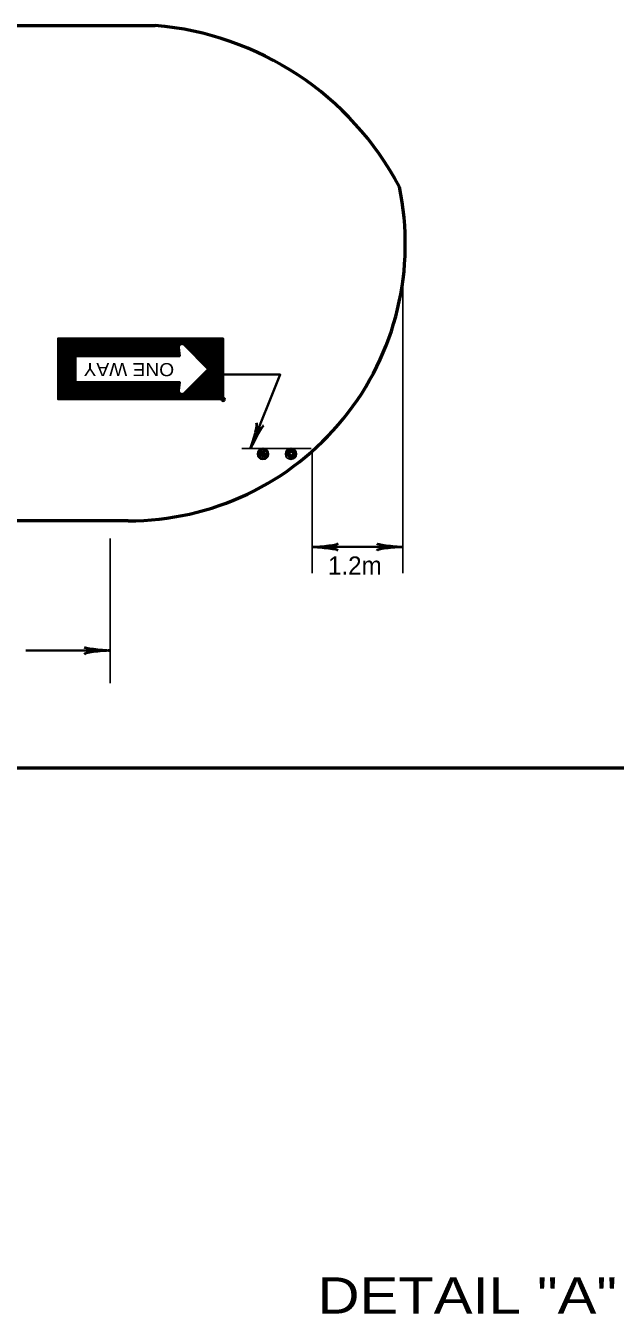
# Model space of a CAD drawing. Extents: x -198 to 658, y -402 to 142.
# Drawn here: x -14.1 to 64.2, y -213 to -43.8 of the extents above; entities that cross this region are included whole.
import ezdxf
from ezdxf.enums import TextEntityAlignment as Align

# ---------------------------------------------------------------- set-up
doc = ezdxf.new("R2010")
doc.units = 0
doc.header["$LTSCALE"] = 0.96
doc.header["$PDMODE"] = 32
doc.header["$PDSIZE"] = 0.48
doc.layers.add('1', color=7, linetype='Continuous', lineweight=35)
doc.layers.add('4', color=7, linetype='Continuous', lineweight=25)

msp = doc.modelspace()

# ---------------------------------------------------------------- linework, layer by layer
at = {"layer": '1', "lineweight": 53}
for p, q in [((-105.2517, -43.8238), (3.1359, -43.8238)), ((-0.4604, -109.4838), (-56.3544, -109.4838)), ((-105.2517, -142.2238), (234.6408, -142.2238))]:
    msp.add_line(p, q, dxfattribs=at)
at = {"layer": '1', "lineweight": 25}
for p, q in [((35.9565, -116.4304), (35.9565, -77.8663)), ((23.8168, -99.9048), (14.6368, -99.9048)), ((23.9356, -116.4304), (23.9356, -100.2786)), ((-2.849, -131.0158), (-2.849, -111.8158))]:
    msp.add_line(p, q, dxfattribs=at)
at = {"layer": '1'}
for p, q in [((-5.2152, -85.3175), (-9.7512, -89.8535)), ((-5.3832, -85.3175), (-9.7512, -89.6855)), ((-5.5512, -85.3175), (-9.7512, -89.5175)), ((-5.6952, -85.3175), (-9.7512, -89.3495)), ((-5.8632, -85.3175), (-9.7512, -89.2055)), ((-6.0312, -85.3175), (-9.7512, -89.0375)), ((-6.1992, -85.3175), (-9.7512, -88.8695)), ((-6.3432, -85.3175), (-9.7512, -88.7015)), ((-6.5112, -85.3175), (-9.7512, -88.5335)), ((-6.6792, -85.3175), (-9.7512, -88.3895)), ((-6.8472, -85.3175), (-9.7512, -88.2215)), ((-7.0152, -85.3175), (-9.7512, -88.0535)), ((-7.1592, -85.3175), (-9.7512, -87.8855)), ((-7.3272, -85.3175), (-9.7512, -87.7175)), ((-7.4952, -85.3175), (-9.7512, -87.5735)), ((-7.6632, -85.3175), (-9.7512, -87.4055)), ((-7.8312, -85.3175), (-9.7512, -87.2375)), ((-7.9752, -85.3175), (-9.7512, -87.0695)), ((-8.1432, -85.3175), (-9.7512, -86.9255)), ((-8.3112, -85.3175), (-9.7512, -86.7575)), ((-8.4792, -85.3175), (-9.7512, -86.5895)), ((-8.6232, -85.3175), (-9.7512, -86.4215)), ((-8.7912, -85.3175), (-9.7512, -86.2535)), ((-8.9592, -85.3175), (-9.7512, -86.1095)), ((-9.1272, -85.3175), (-9.7512, -85.9415)), ((-9.2952, -85.3175), (-9.7512, -85.7735)), ((-9.4392, -85.3175), (-9.7512, -85.6055)), ((-9.6072, -85.3175), (-9.7512, -85.4375)), ((-5.0472, -85.3175), (-7.3752, -87.6455)), ((-4.8792, -85.3175), (-7.2072, -87.6455)), ((-4.7352, -85.3175), (-7.0392, -87.6455)), ((-4.5672, -85.3175), (-6.8952, -87.6455)), ((-4.3992, -85.3175), (-6.7272, -87.6455)), ((-4.2312, -85.3175), (-6.5592, -87.6455)), ((-4.0632, -85.3175), (-6.3912, -87.6455)), ((-3.9192, -85.3175), (-6.2472, -87.6455)), ((-3.7512, -85.3175), (-6.0792, -87.6455)), ((-3.5832, -85.3175), (-5.9112, -87.6455)), ((-3.4152, -85.3175), (-5.7432, -87.6455)), ((-3.2472, -85.3175), (-5.5752, -87.6455)), ((-3.1032, -85.3175), (-5.4312, -87.6455)), ((-2.9352, -85.3175), (-5.2632, -87.6455)), ((-2.7672, -85.3175), (-5.0952, -87.6455)), ((-2.5992, -85.3175), (-4.9272, -87.6455)), ((-2.4552, -85.3175), (-4.7592, -87.6455)), ((-2.2872, -85.3175), (-4.6152, -87.6455)), ((-2.1192, -85.3175), (-4.4472, -87.6455)), ((-1.9512, -85.3175), (-4.2792, -87.6455)), ((-1.7832, -85.3175), (-4.1112, -87.6455)), ((-1.6392, -85.3175), (-3.9432, -87.6455)), ((-1.4712, -85.3175), (-3.7992, -87.6455)), ((-1.3032, -85.3175), (-3.6312, -87.6455)), ((-1.1352, -85.3175), (-3.4632, -87.6455)), ((-0.9672, -85.3175), (-3.2952, -87.6455)), ((-0.8232, -85.3175), (-3.1512, -87.6455)), ((-0.6552, -85.3175), (-2.9832, -87.6455)), ((-0.4872, -85.3175), (-2.8152, -87.6455)), ((-0.3192, -85.3175), (-2.6472, -87.6455)), ((-0.1752, -85.3175), (-2.4792, -87.6455)), ((-0.0072, -85.3175), (-2.3352, -87.6455)), ((0.1608, -85.3175), (-2.1672, -87.6455)), ((0.3288, -85.3175), (-1.9992, -87.6455)), ((0.4968, -85.3175), (-1.8312, -87.6455)), ((0.6408, -85.3175), (-1.6632, -87.6455)), ((0.8088, -85.3175), (-1.5192, -87.6455)), ((0.9768, -85.3175), (-1.3512, -87.6455)), ((1.1448, -85.3175), (-1.1832, -87.6455)), ((1.3128, -85.3175), (-1.0152, -87.6455)), ((1.4568, -85.3175), (-0.8712, -87.6455)), ((1.6248, -85.3175), (-0.7032, -87.6455)), ((1.7928, -85.3175), (-0.5352, -87.6455)), ((1.9608, -85.3175), (-0.3672, -87.6455)), ((2.1288, -85.3175), (-0.1992, -87.6455)), ((2.2728, -85.3175), (-0.0552, -87.6455)), ((2.4408, -85.3175), (0.1128, -87.6455)), ((2.6088, -85.3175), (0.2808, -87.6455)), ((2.7768, -85.3175), (0.4488, -87.6455)), ((2.9208, -85.3175), (0.6168, -87.6455)), ((3.0888, -85.3175), (0.7608, -87.6455)), ((3.2568, -85.3175), (0.9288, -87.6455)), ((3.4248, -85.3175), (1.0968, -87.6455)), ((3.5928, -85.3175), (1.2648, -87.6455)), ((3.7368, -85.3175), (1.4328, -87.6455)), ((3.9048, -85.3175), (1.5768, -87.6455)), ((4.0728, -85.3175), (1.7448, -87.6455)), ((4.2408, -85.3175), (1.9128, -87.6455)), ((4.4088, -85.3175), (2.0808, -87.6455)), ((4.5528, -85.3175), (2.2248, -87.6455)), ((4.7208, -85.3175), (2.3928, -87.6455)), ((4.8888, -85.3175), (2.5608, -87.6455)), ((5.0568, -85.3175), (2.7288, -87.6455)), ((5.2248, -85.3175), (2.8968, -87.6455)), ((5.3688, -85.3175), (3.0408, -87.6455)), ((5.5368, -85.3175), (3.2088, -87.6455)), ((5.7048, -85.3175), (3.3768, -87.6455)), ((5.8728, -85.3175), (3.5448, -87.6455)), ((6.0168, -85.3175), (3.7128, -87.6455)), ((6.1848, -85.3175), (3.8568, -87.6455)), ((6.3528, -85.3175), (4.0248, -87.6455)), ((6.5208, -85.3175), (4.1928, -87.6455)), ((6.6888, -85.3175), (4.3608, -87.6455)), ((6.8328, -85.3175), (4.5288, -87.6455)), ((7.0008, -85.3175), (4.6728, -87.6455)), ((7.1688, -85.3175), (4.8408, -87.6455)), ((7.3368, -85.3175), (6.5928, -86.0615)), ((7.5048, -85.3175), (6.7608, -86.0615)), ((7.6488, -85.3175), (6.8808, -86.0855)), ((6.9048, -86.1095), (10.1688, -89.3735)), ((7.8168, -85.3175), (6.9528, -86.1575)), ((7.9848, -85.3175), (7.0488, -86.2535)), ((8.1528, -85.3175), (7.1208, -86.3255)), ((8.2968, -85.3175), (7.2168, -86.4215)), ((8.4648, -85.3175), (7.2888, -86.4935)), ((8.6328, -85.3175), (7.3608, -86.5655)), ((8.8008, -85.3175), (7.4568, -86.6615)), ((8.9688, -85.3175), (7.5288, -86.7335)), ((9.1128, -85.3175), (7.6248, -86.8295)), ((9.2808, -85.3175), (7.6968, -86.9015)), ((9.4488, -85.3175), (7.7688, -86.9735)), ((9.6168, -85.3175), (7.8648, -87.0695)), ((9.7848, -85.3175), (7.9368, -87.1415)), ((9.9288, -85.3175), (8.0328, -87.2375)), ((10.0968, -85.3175), (8.1048, -87.3095)), ((10.2648, -85.3175), (8.1768, -87.3815)), ((10.4328, -85.3175), (8.2728, -87.4775)), ((10.6008, -85.3175), (8.3448, -87.5495)), ((10.7448, -85.3175), (8.4408, -87.6455)), ((10.9128, -85.3175), (8.5128, -87.7175)), ((11.0808, -85.3175), (8.5848, -87.7895)), ((11.2488, -85.3175), (8.6808, -87.8855)), ((11.3928, -85.3175), (8.7528, -87.9575)), ((11.5608, -85.3175), (8.8488, -88.0295)), ((11.7288, -85.3175), (8.9208, -88.1255)), ((11.8968, -85.3175), (8.9928, -88.1975)), ((12.0648, -85.3175), (9.0888, -88.2935)), ((12.1368, -85.3895), (9.1608, -88.3655)), ((12.1368, -85.5575), (9.2568, -88.4375)), ((12.1368, -85.7255), (9.3288, -88.5335)), ((12.1368, -85.8695), (9.4008, -88.6055)), ((12.1368, -86.0375), (9.4968, -88.7015)), ((12.1368, -86.2055), (9.5688, -88.7735)), ((-7.4472, -87.7175), (-9.7512, -90.0215)), ((-7.4472, -87.8855), (-9.7512, -90.1655)), ((6.2808, -86.3735), (5.0088, -87.6455)), ((6.2808, -86.5415), (5.1768, -87.6455)), ((6.2808, -86.6855), (5.3208, -87.6455)), ((6.3048, -86.8295), (5.4888, -87.6455)), ((6.3048, -86.9735), (5.6568, -87.6455)), ((6.3288, -87.1415), (5.8248, -87.6455)), ((6.3288, -87.2855), (5.9928, -87.6455)), ((6.3528, -87.4295), (6.1368, -87.6455)), ((12.1368, -87.5015), (6.2808, -93.3815)), ((6.3528, -87.5735), (6.3048, -87.6455)), ((12.1368, -87.6695), (6.4248, -93.3815)), ((12.1368, -87.8375), (6.5928, -93.3815)), ((12.1368, -86.3735), (9.6408, -88.8455)), ((12.1368, -86.5415), (9.7368, -88.9415)), ((12.1368, -86.6855), (9.8088, -89.0135)), ((12.1368, -86.8535), (9.9048, -89.1095)), ((12.1368, -87.0215), (9.9768, -89.1815)), ((12.1368, -87.1895), (10.0488, -89.2535)), ((12.1368, -87.3575), (10.1448, -89.3495)), ((-7.4472, -88.0535), (-9.7512, -90.3335)), ((-7.4472, -88.1975), (-9.7512, -90.5015)), ((-7.4472, -88.3655), (-9.7512, -90.6695)), ((-7.4472, -88.5335), (-9.7512, -90.8135)), ((-7.4472, -88.7015), (-9.7512, -90.9815)), ((-7.4472, -88.8455), (-9.7512, -91.1495)), ((-7.4472, -89.0135), (-9.7512, -91.3175)), ((-7.4472, -89.1815), (-9.7512, -91.4855)), ((-7.4472, -89.3495), (-9.7512, -91.6295)), ((-7.4472, -89.5175), (-9.7512, -91.7975)), ((12.1368, -88.0055), (6.7608, -93.3815)), ((10.1688, -89.3735), (6.9048, -92.6135)), ((12.1368, -88.1495), (6.9288, -93.3815)), ((12.1368, -88.3175), (7.0968, -93.3815)), ((12.1368, -88.4855), (7.2408, -93.3815)), ((12.1368, -88.6535), (7.4088, -93.3815)), ((12.1368, -88.8215), (7.5768, -93.3815)), ((12.1368, -88.9655), (7.7448, -93.3815)), ((12.1368, -89.1335), (7.9128, -93.3815)), ((12.1368, -89.3015), (8.0568, -93.3815)), ((12.1368, -89.4695), (8.2248, -93.3815)), ((12.1368, -89.6375), (8.3928, -93.3815)), ((-7.4472, -89.6615), (-9.7512, -91.9655)), ((-7.4472, -89.8295), (-9.7512, -92.1335)), ((-7.4472, -89.9975), (-9.7512, -92.3015)), ((-7.4472, -90.1655), (-9.7512, -92.4455)), ((-7.4472, -90.3335), (-9.7512, -92.6135)), ((-7.4472, -90.4775), (-9.7512, -92.7815)), ((-7.4472, -90.6455), (-9.7512, -92.9495)), ((-7.4472, -90.8135), (-9.7512, -93.1175)), ((-7.4472, -90.9815), (-9.7512, -93.2615)), ((-7.3992, -91.1015), (-9.7032, -93.3815)), ((-7.2552, -91.1015), (-9.5352, -93.3815)), ((-7.0872, -91.1015), (-9.3672, -93.3815)), ((-6.9192, -91.1015), (-9.1992, -93.3815)), ((-6.7512, -91.1015), (-9.0312, -93.3815)), ((-6.6072, -91.1015), (-8.8872, -93.3815)), ((-6.4392, -91.1015), (-8.7192, -93.3815)), ((-6.2712, -91.1015), (-8.5512, -93.3815)), ((-6.1032, -91.1015), (-8.3832, -93.3815)), ((-5.9352, -91.1015), (-8.2392, -93.3815)), ((-5.7912, -91.1015), (-8.0712, -93.3815)), ((-5.6232, -91.1015), (-7.9032, -93.3815)), ((-5.4552, -91.1015), (-7.7352, -93.3815)), ((-5.2872, -91.1015), (-7.5672, -93.3815)), ((-5.1192, -91.1015), (-7.4232, -93.3815)), ((-4.9752, -91.1015), (-7.2552, -93.3815)), ((-4.8072, -91.1015), (-7.0872, -93.3815)), ((-4.6392, -91.1015), (-6.9192, -93.3815)), ((-4.4712, -91.1015), (-6.7512, -93.3815)), ((-4.3272, -91.1015), (-6.6072, -93.3815)), ((-4.1592, -91.1015), (-6.4392, -93.3815)), ((-3.9912, -91.1015), (-6.2712, -93.3815)), ((-3.8232, -91.1015), (-6.1032, -93.3815)), ((-3.6552, -91.1015), (-5.9352, -93.3815)), ((-3.5112, -91.1015), (-5.7912, -93.3815)), ((-3.3432, -91.1015), (-5.6232, -93.3815)), ((-3.1752, -91.1015), (-5.4552, -93.3815)), ((-3.0072, -91.1015), (-5.2872, -93.3815)), ((-2.8392, -91.1015), (-5.1432, -93.3815)), ((-2.6952, -91.1015), (-4.9752, -93.3815)), ((-2.5272, -91.1015), (-4.8072, -93.3815)), ((-2.3592, -91.1015), (-4.6392, -93.3815)), ((-2.1912, -91.1015), (-4.4712, -93.3815)), ((-2.0232, -91.1015), (-4.3272, -93.3815)), ((-1.8792, -91.1015), (-4.1592, -93.3815)), ((-1.7112, -91.1015), (-3.9912, -93.3815)), ((-1.5432, -91.1015), (-3.8232, -93.3815)), ((-1.3752, -91.1015), (-3.6552, -93.3815)), ((-1.2312, -91.1015), (-3.5112, -93.3815)), ((-1.0632, -91.1015), (-3.3432, -93.3815)), ((-0.8952, -91.1015), (-3.1752, -93.3815)), ((-0.7272, -91.1015), (-3.0072, -93.3815)), ((-0.5592, -91.1015), (-2.8392, -93.3815)), ((-0.4152, -91.1015), (-2.6952, -93.3815)), ((-0.2472, -91.1015), (-2.5272, -93.3815)), ((-0.0792, -91.1015), (-2.3592, -93.3815)), ((0.0888, -91.1015), (-2.1912, -93.3815)), ((0.2568, -91.1015), (-2.0472, -93.3815)), ((0.4008, -91.1015), (-1.8792, -93.3815)), ((0.5688, -91.1015), (-1.7112, -93.3815)), ((0.7368, -91.1015), (-1.5432, -93.3815)), ((0.9048, -91.1015), (-1.3752, -93.3815)), ((1.0728, -91.1015), (-1.2312, -93.3815)), ((1.2168, -91.1015), (-1.0632, -93.3815)), ((1.3848, -91.1015), (-0.8952, -93.3815)), ((1.5528, -91.1015), (-0.7272, -93.3815)), ((1.7208, -91.1015), (-0.5592, -93.3815)), ((1.8648, -91.1015), (-0.4152, -93.3815)), ((2.0328, -91.1015), (-0.2472, -93.3815)), ((2.2008, -91.1015), (-0.0792, -93.3815)), ((2.3688, -91.1015), (0.0888, -93.3815)), ((2.5368, -91.1015), (0.2328, -93.3815)), ((2.6808, -91.1015), (0.4008, -93.3815)), ((2.8488, -91.1015), (0.5688, -93.3815)), ((3.0168, -91.1015), (0.7368, -93.3815)), ((3.1848, -91.1015), (0.9048, -93.3815)), ((3.3528, -91.1015), (1.0488, -93.3815)), ((3.4968, -91.1015), (1.2168, -93.3815)), ((3.6648, -91.1015), (1.3848, -93.3815)), ((3.8328, -91.1015), (1.5528, -93.3815)), ((4.0008, -91.1015), (1.7208, -93.3815)), ((4.1448, -91.1015), (1.8648, -93.3815)), ((4.3128, -91.1015), (2.0328, -93.3815)), ((4.4808, -91.1015), (2.2008, -93.3815)), ((4.6488, -91.1015), (2.3688, -93.3815)), ((4.8168, -91.1015), (2.5368, -93.3815)), ((4.9608, -91.1015), (2.6808, -93.3815)), ((5.1288, -91.1015), (2.8488, -93.3815)), ((5.2968, -91.1015), (3.0168, -93.3815)), ((5.4648, -91.1015), (3.1848, -93.3815)), ((5.6328, -91.1015), (3.3288, -93.3815)), ((5.7768, -91.1015), (3.4968, -93.3815)), ((5.9448, -91.1015), (3.6648, -93.3815)), ((6.1128, -91.1015), (3.8328, -93.3815)), ((6.2808, -91.1015), (4.0008, -93.3815)), ((6.3528, -91.1735), (4.1448, -93.3815)), ((6.3528, -91.3415), (4.3128, -93.3815)), ((12.1368, -89.7815), (8.5608, -93.3815)), ((12.1368, -89.9495), (8.7048, -93.3815)), ((12.1368, -90.1175), (8.8728, -93.3815)), ((12.1368, -90.2855), (9.0408, -93.3815)), ((12.1368, -90.4535), (9.2088, -93.3815)), ((12.1368, -90.5975), (9.3768, -93.3815)), ((12.1368, -90.7655), (9.5208, -93.3815)), ((12.1368, -90.9335), (9.6888, -93.3815)), ((12.1368, -91.1015), (9.8568, -93.3815)), ((12.1368, -91.2455), (10.0248, -93.3815)), ((6.3288, -91.5335), (4.4808, -93.3815)), ((6.3048, -91.7015), (4.6488, -93.3815)), ((6.3048, -91.8935), (4.8168, -93.3815)), ((6.2808, -92.0615), (4.9608, -93.3815)), ((6.2568, -92.2295), (5.1288, -93.3815)), ((6.2808, -92.3975), (5.2968, -93.3815)), ((6.3288, -92.4935), (5.4648, -93.3815)), ((6.4248, -92.5895), (5.6088, -93.3815)), ((6.5208, -92.6375), (5.7768, -93.3815)), ((6.6408, -92.6855), (5.9448, -93.3815)), ((6.8328, -92.6615), (6.1128, -93.3815)), ((12.1368, -91.4135), (10.1928, -93.3815)), ((12.1368, -91.5815), (10.3368, -93.3815)), ((12.1368, -91.7495), (10.5048, -93.3815)), ((12.1368, -91.9175), (10.6728, -93.3815)), ((12.1368, -92.0615), (10.8408, -93.3815)), ((12.1368, -92.2295), (11.0088, -93.3815)), ((12.1368, -92.3975), (11.1528, -93.3815)), ((12.1368, -92.5655), (11.3208, -93.3815)), ((12.1368, -92.7335), (11.4888, -93.3815)), ((12.1368, -92.8775), (11.6568, -93.3815)), ((12.1368, -93.0455), (11.8008, -93.3815)), ((12.1368, -93.2135), (11.9688, -93.3815)), ((23.9356, -112.9574), (35.9565, -112.9574)), ((-14.0397, -126.6887), (-2.849, -126.6887))]:
    msp.add_line(p, q, dxfattribs=at)
msp.add_lwpolyline([(12.1368, -93.3815), (-9.7512, -93.3815), (-9.7512, -85.3175), (12.1368, -85.3175)], close=True, dxfattribs=at)
for points in [[(6.2568, -92.2295), (6.3768, -91.1015), (-7.4472, -91.1015), (-7.4472, -87.6455), (6.3768, -87.6455), (6.2568, -86.4935)], [(15.7686, -99.9048), (19.704, -90.1123), (12.1368, -90.1123)]]:
    msp.add_lwpolyline(points, dxfattribs=at)
at = {"layer": '1', "lineweight": 53}
for centre, radius, start, end in [((-0.2045, -84.071), 40.3856, 27.83224, 85.25551), ((-0.361, -72.8171), 36.6668, 269.84467, 11.96498)]:
    msp.add_arc(centre, radius, start, end, dxfattribs=at)
at = {"layer": '1'}
for centre, start, end in [((6.686, -86.4648), 58.76645, 183.36449), ((6.686, -92.2651), 176.63551, 301.23355)]:
    msp.add_arc(centre, 0.419, start, end, dxfattribs=at)
at = {"layer": '1', "lineweight": 40}
for centre, major_axis, ratio, start_param, end_param in [((15.9492, -98.5662), (-0.6252, -2.0582), 0.122415, 0.89635335, 3.14159265), ((16.5056, -98.7519), (-0.9815, -1.8771), 0.07063, 3.14071475, 5.41810995), ((25.2802, -113.2113), (-2.1077, 0.2108), 0.07063, 3.14071475, 5.41810995), ((25.2802, -113.2113), (-2.1077, 0.2108), 0.07063, 3.14071475, 5.41810995), ((25.245, -112.6258), (-2.1428, -0.1874), 0.122415, 0.89635335, 3.14159265), ((25.245, -112.6258), (-2.1428, -0.1874), 0.122415, 0.89635335, 3.14159265), ((34.6471, -113.289), (2.1428, 0.1874), 0.122415, 0.89635335, 3.14159265), ((34.6119, -112.7035), (2.1077, -0.2108), 0.07063, 3.14071475, 5.41810995), ((-4.1584, -127.0203), (2.1428, 0.1874), 0.122415, 0.89635335, 3.14159265), ((-4.1936, -126.4348), (2.1077, -0.2108), 0.07063, 3.14071475, 5.41810995)]:
    msp.add_ellipse(centre, major_axis=major_axis, ratio=ratio, start_param=start_param, end_param=end_param, dxfattribs=at)
at = {"layer": '1', "lineweight": 25}
for points in [[(17.4808, -100.0488), (17.8408, -100.3008), (18.0208, -100.6608), (17.9128, -100.9128), (17.5168, -101.1648), (17.1208, -101.1648), (16.7248, -100.7688), (16.9768, -100.3008), (17.4808, -100.0488), (17.6968, -100.1928), (17.8768, -100.3008), (17.9488, -100.6248), (17.6968, -101.0568), (17.5528, -101.2368), (17.0488, -100.9488), (17.1208, -100.5888), (17.1928, -100.3728), (17.3368, -100.3008), (17.5528, -100.3008), (17.6608, -100.5168), (17.6968, -100.9128), (17.4448, -100.9128), (17.2648, -100.9488), (17.1208, -100.7328), (17.3728, -100.4088), (17.5888, -100.5528), (17.6248, -100.6968), (17.3728, -100.7328), (17.4088, -100.8048), (16.8688, -100.4088), (17.3368, -101.2728), (17.4448, -100.7688), (17.7688, -101.0928), (18.1288, -100.5888), (17.3728, -100.7328), (17.5168, -100.2648), (17.0128, -100.3728), (17.3728, -100.7328)], [(21.1168, -99.9768), (21.5128, -100.1568), (21.7648, -100.5528), (21.6928, -100.9848), (21.2248, -101.2728), (20.7928, -101.0208), (20.5408, -100.6608), (20.6128, -100.4088), (21.1168, -99.9768), (21.3688, -100.2648), (21.5848, -100.3728), (21.6208, -100.5888), (21.3688, -101.0928), (21.1168, -101.0568), (20.9368, -100.9128), (20.6488, -100.7328), (20.8648, -100.3008), (21.1528, -100.2288), (21.3328, -100.3728), (21.4408, -100.5888), (21.3688, -100.8048), (21.2968, -100.9488), (20.9368, -100.8408), (21.0088, -100.5888), (21.0088, -100.4448), (21.2968, -100.4448), (21.3688, -100.6608), (20.9728, -100.8048), (20.9008, -100.7688), (20.5768, -100.4448), (21.0448, -101.1288), (20.9368, -100.8048), (21.4768, -101.1648), (21.7288, -100.5528), (20.9728, -100.8048), (20.9368, -100.1568), (20.8288, -100.3008), (20.9728, -100.8048)]]:
    msp.add_spline(points, degree=3, dxfattribs=at)
at = {"layer": '1'}
msp.add_point((12.1368, -93.3815), dxfattribs=at)
at = {"layer": '4'}
for centre in [(17.423, -100.6133), (21.1252, -100.613)]:
    msp.add_circle(centre, 0.738, dxfattribs=at)

# ---------------------------------------------------------------- texts
at = {"layer": '1', "width": 1.1}
msp.add_text('ONE WAY', height=1.728, rotation=180, dxfattribs=at).set_placement((-0.3676, -88.5815), align=Align.CENTER)
at = {"layer": '1'}
msp.add_text('1.2m', height=2.4, dxfattribs=at).set_placement((29.6075, -116.6135), align=Align.CENTER)
at = {"layer": '1', "width": 1.2}
msp.add_text('DETAIL "A"', height=4.8, dxfattribs=at).set_placement((44.5229, -214.5917), align=Align.CENTER)

doc.saveas('drawing.dxf')
